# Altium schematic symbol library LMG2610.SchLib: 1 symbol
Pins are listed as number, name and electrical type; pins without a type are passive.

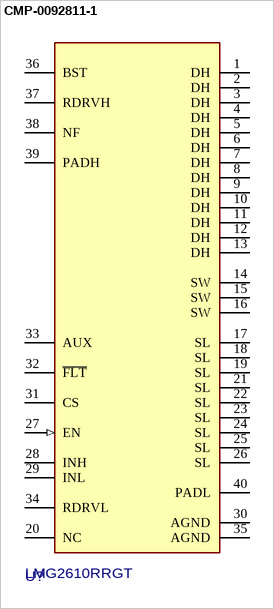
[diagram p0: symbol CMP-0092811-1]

## CMP-0092811-1
designator U?, comment LMG2610RRGT
Integrated 650-V GaN Half-Bridge for Active Clamp Flyback Converters; Manufacturer: Texas Instruments; Turn Off Delay Time: 5ns; Number Of Drivers: 2; Propagation Delay: 50ns; Standoff Height: 0mm; SizeZ_mm: 1mm; Min Supply Voltage: 10V; Output Voltage: 650V; Max Supply Voltage: 26V; TJmax_C: +125°C; AEC Qualified: No
footprint RRG0038A-MFG
pins: 1 DH (power), 2 DH (power), 3 DH (power), 4 DH (power), 5 DH (power), 6 DH (power), 7 DH (power), 8 DH (power), 9 DH (power), 10 DH (power), 11 DH (power), 12 DH (power), 13 DH (power), 14 SW, 15 SW, 16 SW, 17 SL (power), 18 SL (power), 19 SL (power), 20 NC, 21 SL (power), 22 SL (power), 23 SL (power), 24 SL (power), 25 SL (power), 26 SL (power), 27 EN (in), 28 INH, 29 INL, 30 AGND (power), 31 CS, 32 ~{FLT} (oc), 33 AUX, 34 RDRVL, 35 AGND (power), 36 BST, 37 RDRVH, 38 NF, 39 PADH, 40 PADL (power)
